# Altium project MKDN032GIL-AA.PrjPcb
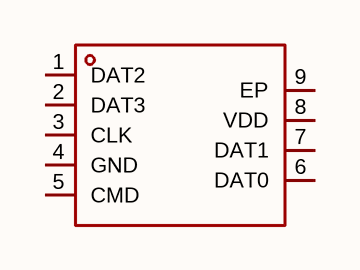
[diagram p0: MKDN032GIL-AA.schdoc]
1 sheet, 1 parts. Net scope: global (net labels, ports and power ports of the same name join across sheets).

## Sheet MKDN032GIL-AA.schdoc
size 127 x 101 mm

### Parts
U?  mkdn032gil-aa  [LGA-16_L12.5-W9.0-P1.27-TL-EP]  (value not drawn)

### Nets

Not connected (* = marked no-connect by the designer): U? 1(DAT2) 2(DAT3) 3(CLK) 4(GND) 5(CMD) 6(DAT0) 7(DAT1) 8(VDD) 9(EP)

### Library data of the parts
U? = mkdn032gil-aa: 存储容量:32Gbit;时钟频率(fc):208MHz;工作电压:2.7V~3.6V;; Manufacturer: MK(米客方德); AddInBom: yes; ModelId: aae4acadbbb4480ebd429fe2f08c27d7; ModelTransform: 492.125,354.33,0,0,0,0,0,0,0; Memory Size: 32Gbit; Interface: SD接口；SPI; Clock Frequency: 208MHz; Standby Supply Current: 250uA; Program / Erase Cycles: 5万次; ECC: 有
